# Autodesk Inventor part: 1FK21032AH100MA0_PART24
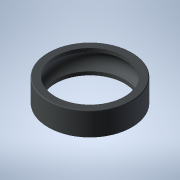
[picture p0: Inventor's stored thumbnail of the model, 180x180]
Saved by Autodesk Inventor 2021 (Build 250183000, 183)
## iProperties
Created: 2025-04
Part Number: 1FK21032AH100MA0_PART24
Material: Generic
Catalog Web Link: www.3dfindit.com
Description: -Servo synchronous motor
Document SubType Name: Modeling
Designer: psAdmin
Mass: 1.46378 g
Surface Area: 23.3636 cm^2
Volume: 1.46378 cm^3
Density: 1 g/cm^3
Appearance: PSOLRGB-212-217-219
Category: PARTsolutions
Title: 1FK21032AH100MA0_PART24
Author: Cadenas PARTsolutions
Comments: Servo synchronous motor
Sending System: PARTsolutions
Preprocessor: ST-DEVELOPER v19.3
PSOL_IDENT_0: {$CADENAS_DATA/23d-libs/siemens_ag/_cat_/12/33/1fk21032ah100ma0.prj},216 {VTYP=3D},{NB=1FK21032AH100
PSOL_IDENT_1: MA0_PART24},{LINA=1FK21032AH100MA0_PART24},{NN=1FK21032AH100MA0_PART24},{NOPRJ=TRUE},{DATE=19.08.202
PSOL_IDENT_2: 5 14:00:27},{GEOMDATE=30.07.2025 02:02:58},{VERSION=},{LINEID=10},{WBVAR=},{WBNUMERIC=}  {NB=1FK2103
PSOL_IDENT_3: 2AH100MA0_PART24},{LINA=1FK21032AH100MA0_PART24},{KT=DUMMY},{PREVIEW=../../../_pool_/d3/78/p_d211_xx
PSOL_IDENT_4: _00934j.png},{DESCSHORT=SIMOTICS S-1FK2 HD, SINAMICS S210 3AC 400V-480V, 0.59 Nm, 4500 rpm},{DESCLON
PSOL_IDENT_5: G=SIMOTICS S-1FK2 HD servo motor M0=0.64 Nm; PN = 0.28 kW at nN=4500 rpm (380-480 V); PN = 0.167 kW
PSOL_IDENT_6: at nN=2500 rpm (200-240 V); with holding brake; degree of protection IP64; cylindrical shaft D14 x 3
PSOL_IDENT_7: 0 mm; absolute encoder 22-bit + 12-bit multiturn (encoder AM22DQC); with OCC interface; plug size M1
PSOL_IDENT_8: 7, rotatable; SIMOTICS S-1FK2 servomotorfor a wide range of uses in industrial environments. SIMOTIC
PSOL_IDENT_9: S S‑1FK2 servomotors are compact synchronous motors with a high dynamic performance that set themsel
PSOL_IDENT_10: ves apart as a result of their high power density, degree of protection and overload capability. The
PSOL_IDENT_11: motors are available in two variants: as High Dynamic variant (highest dynamic performance as a res
PSOL_IDENT_12: ult of the low intrinsic moment of inertia for applications demanding a high dynamic performance wit
PSOL_IDENT_13: h low moved masses) - and as Compact variant (precise and stable closed-loop control for medium up t
PSOL_IDENT_14: o large moved masses as a result of a medium intrinsic moment of inertia). SIMOTICSS‑1FK2 servomotor
PSOL_IDENT_15: s fully exploit their strengths in a system with the SINAMICSS210 frequency converter and simple con
PSOL_IDENT_16: nection using the one cable connection (OCC). Advantages include the short control and positioning t
PSOL_IDENT_17: imes, fast and precise correction of disturbing quantities as well as stable control with a high dyn
PSOL_IDENT_18: amic performance. The servo motors can be configured to address a wide range of requirements. For ex
PSOL_IDENT_19: ample with and without holding brake, IP64 or IP65 degree of protection, singleturn or multiturn abs
PSOL_IDENT_20: olute encoders - to name just a few. Further, the servomotors are available in different shaft heigh
PSOL_IDENT_21: ts extending from 20 to 100. A shaft sealing ring is available to achieve an IP65 degree of protecti
PSOL_IDENT_22: on and for subsequent mounting at the motor or as spare part. SIMOTICS - the optimum motor for each
PSOL_IDENT_23: and every motion control application.},{INTNO=195125315563},{SUPPLIERALTNO=1FK2103-2AH10-0MA0},{MANU
PSOL_IDENT_24: ID=1FK21032AH100MA0},{MANUNAME=Siemens},{MANUTYPEDESC=SYNCHRONOUS MOTOR 1FK2 HD 0,64 NM},{AAU732=SIM
PSOL_IDENT_25: OTICS},{AAO057=S-1FK2},{AAU734=SIMOTICS S-1FK2 HD servo motor M0=0.64 Nm; PN = 0.28 kW at nN=4500 rp
PSOL_IDENT_26: m (380-480 V); PN = 0.167 kW at nN=2500 rpm (200-240 V); with holding brake; degree of protection IP
PSOL_IDENT_27: 64; cylindrical shaft D14 x 30 mm; absolute encoder 22-bit + 12-bit multiturn (encoder AM22DQC); wit
PSOL_IDENT_28: h OCC interface; plug size M17, rotatable;},{AAW338=SYNCHRONOUS MOTOR 1FK2 HD 0,64 NM},{AAO742=SIMOT
PSOL_IDENT_29: ICS},{AAO663=4034106444723},{NOCUPEROU=1},{PRICEQUANTITY=1},{QUANTITYMIN=1},{QUANTITYINT=1},{CTN=850
PSOL_IDENT_30: 15100},{COO=RO},{AAO676=1FK2103-2AH10-0MA0},{AAO677=Siemens AG},{ORDERUNIT=C62},{CONTENTUNIT=C62}
NB: 1FK21032AH100MA0_PART24
NT: Servo synchronous motor
NBSYN: $MANUID._PART24
LINA: 1FK21032AH100MA0_PART24
CATALOG: SIEMENS
PREVIEW: ../../../_pool_/d3/78/p_d211_xx_00934j.png
DESCSHORT: SIMOTICS S-1FK2 HD, SINAMICS S210 3AC 400V-480V, 0.59 Nm, 4500 rpm
DESCLONG: SIMOTICS S-1FK2 HD servo motor M0=0.64 Nm; PN = 0.28 kW at nN=4500 rpm (380-480 V); PN = 0.167 kW at nN=2500 rpm (200-240 V); with holding brake; degree of prot
INTNO: 195125315563
SUPPLIERALTNO: 1FK2103-2AH10-0MA0
MANUID: 1FK21032AH100MA0
MANUNAME: Siemens
MANUTYPEDESC: SYNCHRONOUS MOTOR 1FK2 HD 0,64 NM
AAU732: SIMOTICS
AAO057: S-1FK2
AAU734: SIMOTICS S-1FK2 HD servo motor M0=0.64 Nm; PN = 0.28 kW at nN=4500 rpm (380-480 V); PN = 0.167 kW at nN=2500 rpm (200-240 V); with holding brake; degree of prot
AAW338: SYNCHRONOUS MOTOR 1FK2 HD 0,64 NM
AAO742: SIMOTICS
AAO663: 4034106444723.0
NOCUPEROU: 1
PRICEQUANTITY: 1
QUANTITYMIN: 1
QUANTITYINT: 1
CTN: 85015100
COO: RO
ARTICLENO: 1FK21032AH100MA0_PART24
BOMINFO: 1FK21032AH100MA0_PART24
CREATOR: CADENAS GmbH
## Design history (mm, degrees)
feature "2025_04_17_15_06_16_0705"
body "Solid1"
